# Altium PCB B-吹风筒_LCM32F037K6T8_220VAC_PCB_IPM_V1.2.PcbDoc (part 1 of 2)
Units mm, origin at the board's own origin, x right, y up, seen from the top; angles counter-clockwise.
Board outline 42.33 x 117.1 mm, 2 copper layers (TopLayer, BottomLayer); 131 components, 93 nets, 324 pads, 143 vias.
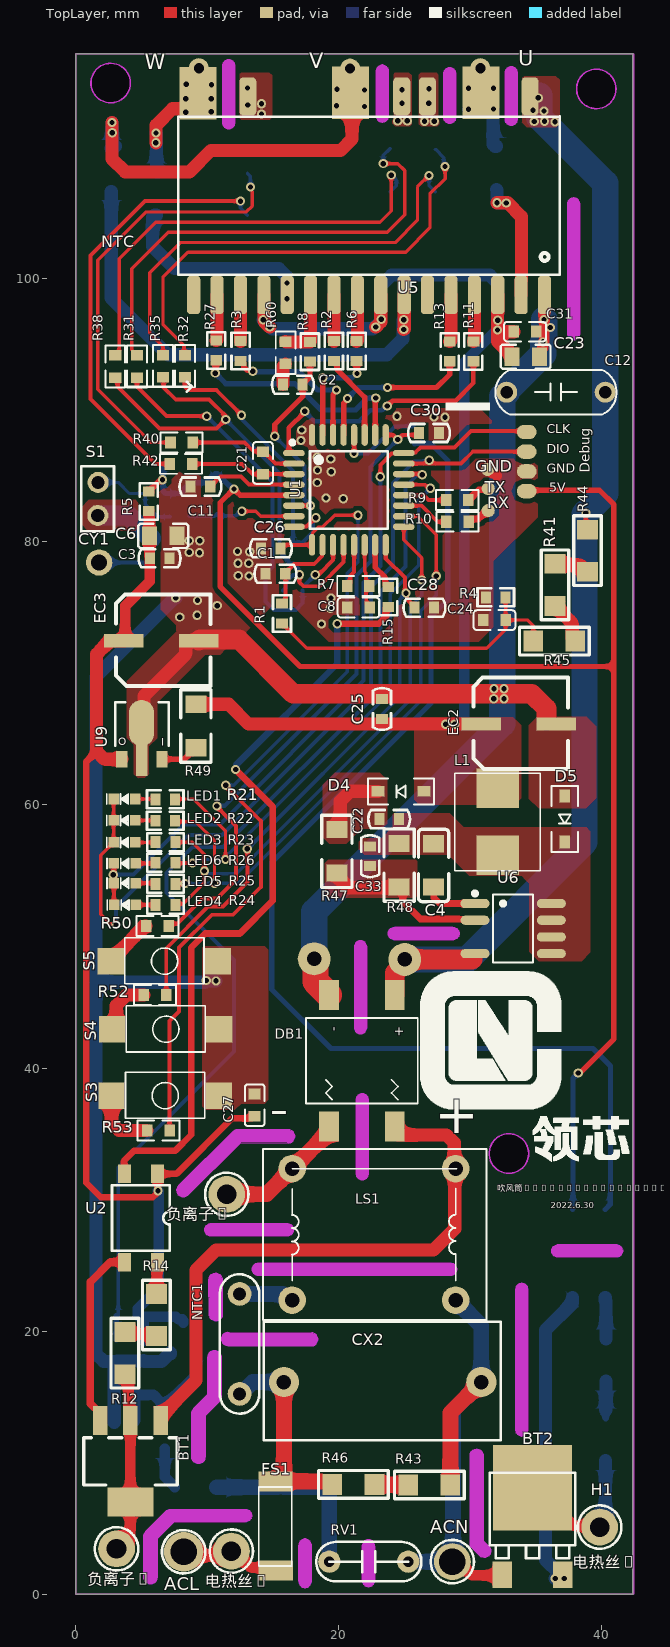
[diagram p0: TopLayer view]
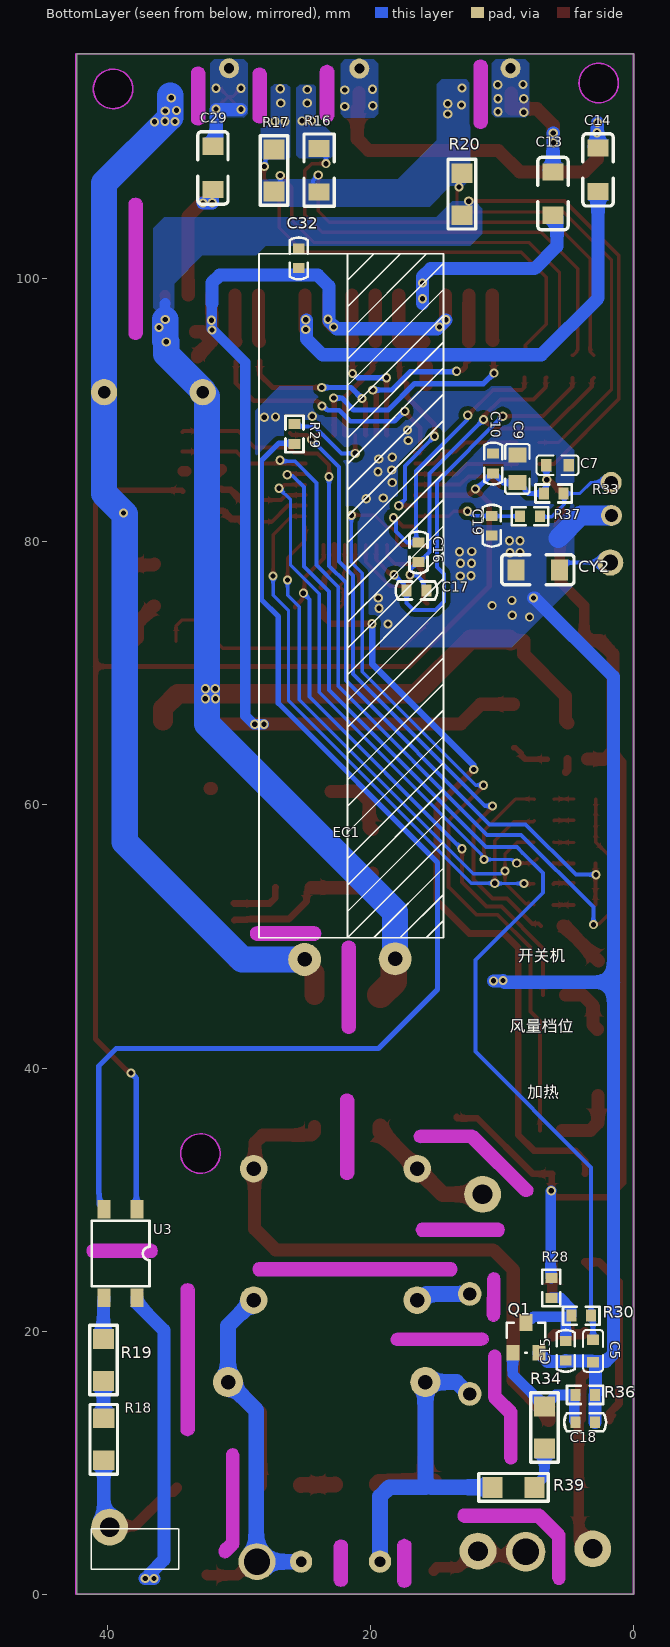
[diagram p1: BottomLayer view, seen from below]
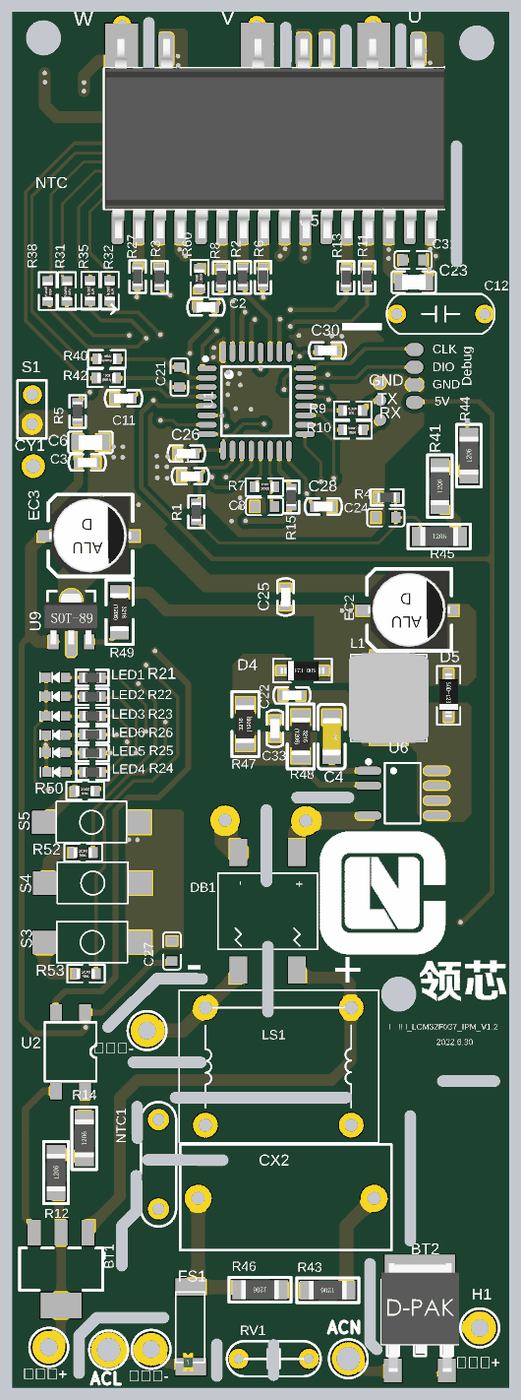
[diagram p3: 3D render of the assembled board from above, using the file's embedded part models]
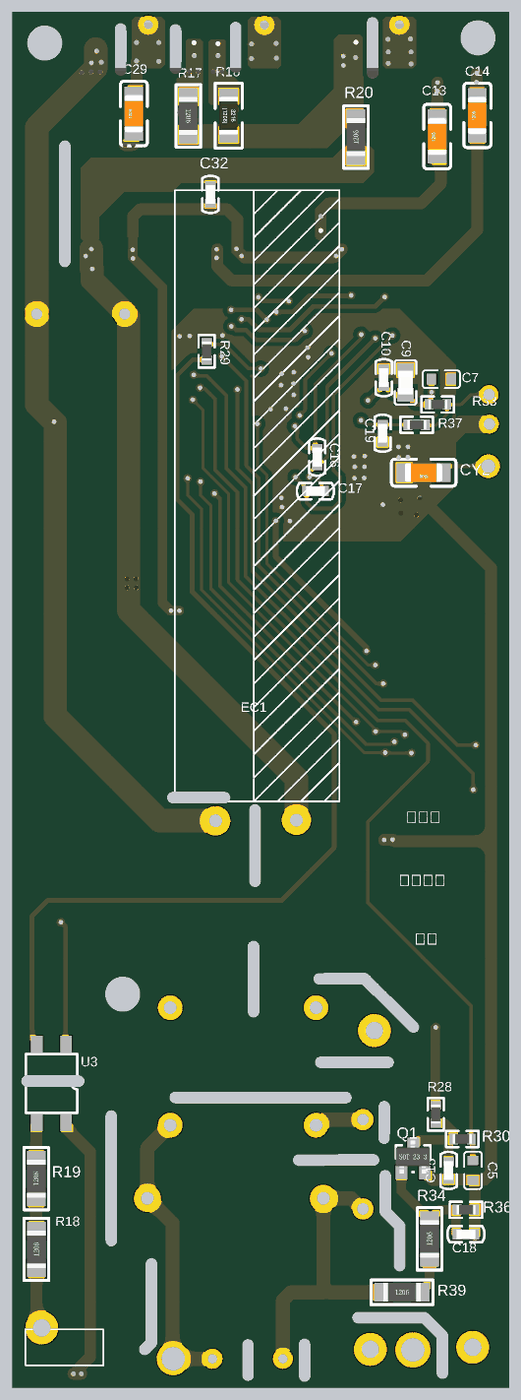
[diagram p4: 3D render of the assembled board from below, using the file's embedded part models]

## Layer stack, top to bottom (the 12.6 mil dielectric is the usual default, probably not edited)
TopSolder: solder mask 0.0102, Solder Resist, Dk 3.5
TopLayer: signal copper 0.035
Dielectric1: dielectric 0.32, FR-4, Dk 4.8
BottomLayer: signal copper 0.035
BottomSolder: solder mask 0.0102, Solder Resist, Dk 3.5

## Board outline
0,0 0,117.1 41,117.1 42.325,117.1 42.325,0
cut-out: 30.121,3.496 cw(c30.475,3.85) 29.975,3.85 29.975,10.55 cw(c30.475,10.55) 30.975,10.55 30.975,4.057 31.404,3.629 cw(c31.05,3.275) 31.55,3.275 cw(c31.05,3.275) 30.696,2.921
cut-out: 5.175,1.25 5.175,4.425 cw(c5.675,4.425) 5.321,4.779 6.871,6.329 cw(c7.225,5.975) 7.225,6.475 12.875,6.475 cw(c12.875,5.975) 13.375,5.975 cw(c12.875,5.975) 12.875,5.475 7.432,5.475 6.175,4.218 6.175,1.25 cw(c5.675,1.25)
cut-out: 21.75,1.075 ccw(c22.25,1.075) 22.75,1.075 22.75,3.65 ccw(c22.25,3.65) 21.75,3.65
cut-out: 16.925,1 ccw(c17.425,1) 17.925,1 17.925,3.7 ccw(c17.425,3.7) 16.925,3.7
cut-out: 7.798,31.056 ccw(c8.15,30.7) 8.502,30.344 12.528,34.322 16.172,34.3 ccw(c16.175,34.8) 16.675,34.8 ccw(c16.175,34.8) 16.178,35.3 12.328,35.324 ccw(c12.324,34.824) 11.972,35.179
cut-out: 11.125,111.9 ccw(c11.625,111.9) 12.125,111.9 12.125,116.15 ccw(c11.625,116.15) 11.125,116.15
cut-out: 8.825,10.4 8.825,13.775 cw(c9.325,13.775) 8.971,14.129 10.05,15.207 10.05,18.05 cw(c10.55,18.05) 11.05,18.05 11.05,15 cw(c10.55,15) 10.904,14.646 9.825,13.568 9.825,10.4 cw(c9.325,10.4)
cut-out: 36.675,25.6 cw(c36.675,26.1) 36.675,26.6 41.075,26.6 cw(c41.075,26.1) 41.575,26.1 cw(c41.075,26.1) 41.075,25.6
cut-out: 33.4,12.525 ccw(c33.9,12.525) 34.4,12.525 34.4,23.125 ccw(c33.9,23.125) 33.4,23.125
cut-out: 10.3,27.2 cw(c10.3,27.7) 10.3,28.2 16.05,28.2 cw(c16.05,27.7) 16.55,27.7 cw(c16.05,27.7) 16.05,27.2
cut-out: 37.35,95.85 ccw(c37.85,95.85) 38.35,95.85 38.35,105.65 ccw(c37.85,105.65) 37.35,105.65
cut-out: 11.548,18.9 17.923,18.875 ccw(c17.925,19.375) 18.425,19.375 ccw(c17.925,19.375) 17.927,19.875 11.552,19.9 ccw(c11.55,19.4)
cut-out: 10.15,21.245 10.125,23.92 cw(c10.625,23.925) 11.125,23.93 11.15,21.255 cw(c10.65,21.252)
cut-out: 31.425,33.5 ccw(c32.925,33.5) 32.925,32 ccw(c32.925,33.5) 34.425,33.5 ccw(c32.925,33.5) 32.925,35 ccw(c32.925,33.5)
cut-out: 38.066,114.428 ccw(c39.566,114.428) 39.566,112.928 ccw(c39.566,114.428) 41.066,114.428 ccw(c39.566,114.428) 39.566,115.928 ccw(c39.566,114.428)
cut-out: 2.65,113.375 cw(c2.65,114.875) 1.15,114.875 cw(c2.65,114.875) 2.65,116.375 cw(c2.65,114.875) 4.15,114.875 cw(c2.65,114.875)
cut-out: 21.275,32 ccw(c21.775,32) 22.275,32 22.275,37.55 ccw(c21.775,37.55) 21.275,37.55
cut-out: 21.15,43.1 ccw(c21.65,43.1) 22.15,43.1 22.15,49.175 ccw(c21.65,49.175) 21.15,49.175
cut-out: 24.25,49.725 cw(c24.25,50.225) 24.25,50.725 28.65,50.725 cw(c28.65,50.225) 29.15,50.225 cw(c28.65,50.225) 28.65,49.725
cut-out: 13.9,24.2 cw(c13.9,24.7) 13.9,25.2 28.45,25.2 cw(c28.45,24.7) 28.95,24.7 cw(c28.45,24.7) 28.45,24.2
cut-out: 27.925,112.3 ccw(c28.425,112.3) 28.925,112.3 28.925,115.55 ccw(c28.425,115.55) 27.925,115.55
cut-out: 32.6,112.15 ccw(c33.1,112.15) 33.6,112.15 33.6,115.625 ccw(c33.1,115.625) 32.6,115.625
cut-out: 22.8,112.4 ccw(c23.3,112.4) 23.8,112.4 23.8,115.75 ccw(c23.3,115.75) 22.8,115.75

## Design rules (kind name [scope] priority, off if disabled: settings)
Clearance [All] p1: gap=0.25 ignorepadtopadclearanceinfootprint=FALSE except(0.35: Arc-Fill Arc-Poly Arc-Region Track-Fill Track-Poly Track-Region SMDPad-Fill SMDPad-Poly SMDPad-Region THPad-Fill THPad-Poly THPad-Region Via-Fill Via-Poly Via-Region Fill-Fill Fill-Poly Fill-Region Poly-Poly Poly-Region Region-Region)
ComponentClearance [All] p1: gap=0 collisioncheckmode=3 verticalgap=2540 showdistances=FALSE
DiffPairsRouting [All] p1: maxlimit=0.254 minlimit=0.254 mostfreqgap=0.254 substack1={7B2B07BE-FECC-4EBA-A35D-CE5C1B368DA4} toplayer_{7b2b07be-fecc-4eba-a35d-ce5c1b368da4}_minwidth=0.381 toplayer_{7b2b07be-fecc-4eba-a35d-ce5c1b368da4}_maxwidth=0.381 toplayer_{7b2b07be-fecc-4eba-a35d-ce5c1b368da4}_prefwidth=0.381 bottomlayer_{7b2b07be-fecc-4eba-a35d-ce5c1b368da4}_minwidth=0.381 bottomlayer_{7b2b07be-fecc-4eba-a35d-ce5c1b368da4}_maxwidth=0.381 bottomlayer_{7b2b07be-fecc-4eba-a35d-ce5c1b368da4}_prefwidth=0.381 substack2={2A57B4B4-6E69-4721-8056-AED80E470A93} toplayer_{2a57b4b4-6e69-4721-8056-aed80e470a93}_minwidth=0.381 toplayer_{2a57b4b4-6e69-4721-8056-aed80e470a93}_maxwidth=0.381 toplayer_{2a57b4b4-6e69-4721-8056-aed80e470a93}_prefwidth=0.381 bottomlayer_{2a57b4b4-6e69-4721-8056-aed80e470a93}_minwidth=0.381 bottomlayer_{2a57b4b4-6e69-4721-8056-aed80e470a93}_maxwidth=0.381 bottomlayer_{2a57b4b4-6e69-4721-8056-aed80e470a93}_prefwidth=0.381 substack3={97241F62-DD6F-472E-8EB9-D48B5CBCBE02} toplayer_{97241f62-dd6f-472e-8eb9-d48b5cbcbe02}_minwidth=0.381 toplayer_{97241f62-dd6f-472e-8eb9-d48b5cbcbe02}_maxwidth=0.381 toplayer_{97241f62-dd6f-472e-8eb9-d48b5cbcbe02}_prefwidth=0.381 bottomlayer_{97241f62-dd6f-472e-8eb9-d48b5cbcbe02}_minwidth=0.381 bottomlayer_{97241f62-dd6f-472e-8eb9-d48b5cbcbe02}_maxwidth=0.381 bottomlayer_{97241f62-dd6f-472e-8eb9-d48b5cbcbe02}_prefwidth=0.381 substack4={361573DB-5FAD-456A-B524-EEB2E02C5D13} toplayer_{361573db-5fad-456a-b524-eeb2e02c5d13}_minwidth=0.381 toplayer_{361573db-5fad-456a-b524-eeb2e02c5d13}_maxwidth=0.381 toplayer_{361573db-5fad-456a-b524-eeb2e02c5d13}_prefwidth=0.381 bottomlayer_{361573db-5fad-456a-b524-eeb2e02c5d13}_minwidth=0.381 bottomlayer_{361573db-5fad-456a-b524-eeb2e02c5d13}_maxwidth=0.381 bottomlayer_{361573db-5fad-456a-b524-eeb2e02c5d13}_prefwidth=0.381 toplayer_minwidth=0.25 toplayer_maxwidth=0.381 toplayer_prefwidth=0.3 bottomlayer_minwidth=0.25 bottomlayer_maxwidth=0.381 bottomlayer_prefwidth=0.3 substack5={64A2AA3D-35F6-4C37-B5AC-204E40DA3198} toplayer_{64a2aa3d-35f6-4c37-b5ac-204e40da3198}_minwidth=0.381 toplayer_{64a2aa3d-35f6-4c37-b5ac-204e40da3198}_maxwidth=0.381 toplayer_{64a2aa3d-35f6-4c37-b5ac-204e40da3198}_prefwidth=0.381 bottomlayer_{64a2aa3d-35f6-4c37-b5ac-204e40da3198}_minwidth=0.381 bottomlayer_{64a2aa3d-35f6-4c37-b5ac-204e40da3198}_maxwidth=0.381 bottomlayer_{64a2aa3d-35f6-4c37-b5ac-204e40da3198}_prefwidth=0.381 substack6={DDE46566-CA28-4514-92A2-DCCB6BB664C3} toplayer_{dde46566-ca28-4514-92a2-dccb6bb664c3}_minwidth=0.381 toplayer_{dde46566-ca28-4514-92a2-dccb6bb664c3}_maxwidth=0.381 toplayer_{dde46566-ca28-4514-92a2-dccb6bb664c3}_prefwidth=0.381 bottomlayer_{dde46566-ca28-4514-92a2-dccb6bb664c3}_minwidth=0.381 bottomlayer_{dde46566-ca28-4514-92a2-dccb6bb664c3}_maxwidth=0.381 bottomlayer_{dde46566-ca28-4514-92a2-dccb6bb664c3}_prefwidth=0.381 substack7={F3E6C291-C9AD-4F5A-A66D-27B9332EED3B} toplayer_{f3e6c291-c9ad-4f5a-a66d-27b9332eed3b}_minwidth=0.381 toplayer_{f3e6c291-c9ad-4f5a-a66d-27b9332eed3b}_maxwidth=0.381 toplayer_{f3e6c291-c9ad-4f5a-a66d-27b9332eed3b}_prefwidth=0.381 bottomlayer_{f3e6c291-c9ad-4f5a-a66d-27b9332eed3b}_minwidth=0.381 bottomlayer_{f3e6c291-c9ad-4f5a-a66d-27b9332eed3b}_maxwidth=0.381 bottomlayer_{f3e6c291-c9ad-4f5a-a66d-27b9332eed3b}_prefwidth=0.381 maxuncoupledlength=12.7
FabricationTestPointUsage TestPointUsage [All] p1: valid=0 allowmultiple=FALSE
FabricationTestpoint Testpoint [All] p1: side=3 testpointundercomponent=TRUE minsize=1.016 maxsize=2.54 preferedsize=1.524 minholesize=0.508 maxholesize=1.016 preferedholesize=0.813 testpointgrid=0.025 allowsidetop=TRUE allowsidebottom=TRUE usegrid=TRUE gridtolerance=0
PolygonConnect [All] p1: connectstyle=Direct reliefconductorwidth=0.254 reliefentries=4 polygonreliefangle="90 Angle" airgapwidth=0.254
RoutingVias [All] p1: holewidth=0.711 width=1.27 viastyle="Through Hole" minholewidth=0.711 minwidth=1.27 maxholewidth=0.711 maxwidth=1.27
SolderMaskExpansion [All] p1: expansion=0.102 istentingtop=FALSE
Width [All] p1: maxlimit=4 minlimit=0.2 preferedwidth=0.254 substack1={7B2B07BE-FECC-4EBA-A35D-CE5C1B368DA4} substack2={2A57B4B4-6E69-4721-8056-AED80E470A93} substack3={97241F62-DD6F-472E-8EB9-D48B5CBCBE02} substack4={361573DB-5FAD-456A-B524-EEB2E02C5D13} substack5={64A2AA3D-35F6-4C37-B5AC-204E40DA3198} substack6={DDE46566-CA28-4514-92A2-DCCB6BB664C3} substack7={F3E6C291-C9AD-4F5A-A66D-27B9332EED3B}
26 further rules are at their usual default settings.

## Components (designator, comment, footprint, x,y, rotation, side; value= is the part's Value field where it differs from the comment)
ACL "发热丝L" TP1.6#1 8.2,3.225 r0 top (schematic designator L-1)
ACN "" TP1.6#2 28.625,2.475 r0 top (schematic designator N2)
BT1 "BT131-600D/SOT223" SOT-223-3_L6.5-W3.4-P2.30-LS7.0-BR 4.15,10.1 r90 top
BT2 "BT138-800E/TO-252" TO-252 34.725,3.975 r0 top
C1 "103/50V" 0603C#1 14.425,77.575 r0 top
C2 "104/50V" 0603C#1 17.25,91.95 r180 top
C3 "10uF/25V" 0603C#1 5.625,78.75 r0 top
C4 "475/25V" C1206C 27.2,55.4 r270 top
C5 "103/50V" 0603C#2 3.075,18.5 r270 bottom
C6 "10uF/10V" 0805C 5.6,80.45 r0 top
C7 "104/50V" 0603C#2 5.775,85.825 r180 bottom
C8 "105/50V" 0603C#2 21.5,75 r0 top value=104/50V
C9 "10uF/25V" 0805C 8.825,84.5 r90 bottom
C10 "104/50V" 0603C#1 10.675,86.7 r270 bottom
C11 "104/50V" 0603C#1 8.725,84.2 r0 top
C12 "104/500V" CAP7.5 36.5,91.375 r0 top value=104P/1KV
C13 "225/50V" C1206C 6.125,106.475 r90 bottom value=100pF
C14 "225/50V" C1206C 2.7,108.275 r90 bottom value=100pF
C15 "103/50V" 0603C#1 5.15,19.25 r270 bottom
C16 "101/50V" 0603C#1 16.35,79.95 r270 bottom
C17 "101/50V" 0603C#1 17.25,76.3 r180 bottom
C18 "103/50V" 0603C#1 4.425,13.075 r180 bottom
C19 "103/50V" 0603C#1 10.775,80.478 r90 bottom
C21 "101/50V" 0603C#2 14.225,86 r270 top
C22 "105/50V" 0603C#1 23.075,58.925 r0 top
C23 "10uF/50V" 0805C 33.15,94.075 r0 top
C24 "103/50V" 0603C#2 31.825,74.05 r180 top
C25 "104/50V" 0603C#1 23.275,66.55 r90 top
C26 "104/50V" 0603C#1 15.575,79.5 r180 top
C27 "104/50V" 0603C#2 13.6,37.175 r90 top
C28 "104/50V" 0603C#1 25.75,75 r0 top
C29 "225/50V" C1206C 31.975,108.425 r90 bottom value=100pF
C30 "104/50V" 0603C#1 26.1,88.275 r0 top
C31 "10uF/50V" 0603C#2 34.15,95.975 r0 top
C32 "104/50V" 0603C#1 25.45,100.8 r90 bottom
C33 "104/50V" 0603C#1 22.375,56.85 r270 top
CX2 "680nF/310VAC" CX0.58UF280VAC-18*9*15-H 23.325,16.125 r180 top
CY1 "" "TP1.6 - 1" 1.775,78.425 r0 top
CY2 "3.3nF/500V" C1206C 7.275,77.875 r0 bottom
D4 "FR107" D-SOD-123 24.725,61.025 r180 top
D5 "ES2JW/SOD123" D-SOD-123 37.175,58.925 r270 top
DB1 "DB307S" DBG-DB107G-SMD 21.75,40.55 r270 top
Debug "CON4" CN4P1.5- 34.275,86.1 r90 bottom
EC1 "120uF/400V 13*45mm" "120UF/400V D18.3*H51.2" 21.475,49.75 r180 bottom locked
EC2 "220uF/25V" ECT6.3_5.5 30.825,66.15 r0 top
EC3 "220uF/16V" ECT6.3_5.5 3.65,72.475 r0 top
FS1 "3.15贴片" "FU 6*2.5" 15.1,5.3 r90 top
GND "P" P 31.3,85.5 r0 top
H1 "发热丝2" TP1.6#3 39.825,5.1 r0 top
L1 "1mH/250mA" LD7*7-SMD 28.825,62.4 r270 top
LED1 "LED" LED0603S 3.7,60.45 r180 top
LED2 "LED" LED0603S 3.7,58.825 r180 top
LED3 "LED" LED0603S 3.7,57.15 r180 top
LED4 "LED" LED0603S 3.75,52.4 r180 top
LED5 "LED" LED0603S 3.725,54.05 r180 top
LED6 "LED" LED0603S 3.725,55.55 r180 top
LS1 "10MH/10*13" "LF-UU9.8 - 1" 20.45,27.325 r90 top
NTC1 "3D-9" CYNTC-P10-S 12.45,19.025 r270 top
Q1 "3904" SOT23SDG-S 8.175,19.5 r180 bottom
R1 "1K" 0603R 15.675,73.8 r90 top
R2 "51R" 0603R 19.625,95.25 r270 top
R3 "51R" 0603R 12.525,95.25 r270 top
R4 "6.8K 1%" 0603R 31.175,75.775 r0 top
R5 "0R 5%" 0603R 5.55,83.825 r270 top
R6 "51R" 0603R 21.35,95.25 r270 top
R7 "10k1% 0603" R0603R 21.475,76.65 r0 top
R8 "1K" 0603R 17.8,95.2 r270 top
R9 "100R 5%" R0603R 29,83.175 r180 top
R10 "100R 5%" R0603R 29.025,81.525 r180 top
R11 "51R" 0603R 30.225,95.225 r270 top
R12 "220R" 1206R#1 3.725,16.725 r90 top
R13 "51R" 0603R 28.425,95.225 r270 top
R14 "220R" 1206R#1 6.125,19.625 r90 top
R15 "330R" 0603R 23.75,76.55 r270 top
R16 "0.15R 1206" 1206R#2 23.9,108.25 r270 bottom
R17 "0.15R 1206" 1206R#1 27.325,109.825 r270 bottom
R18 "220R" 1206R#1 40.275,10.175 r90 bottom
R19 "220R" 1206R#1 40.3,16.2 r90 bottom
R20 "0.15R 1206" 1206R#1 13.05,104.825 r90 bottom
R21 "1K" 0603R 6.05,60.425 r0 top
R22 "1K" 0603R 6.05,58.8 r0 top
R23 "1K" 0603R 6.075,57.175 r0 top
R24 "1K" 0603R 6.075,52.4 r0 top
R25 "1K" 0603R 6.075,54 r0 top
R26 "1K" 0603R 6.075,55.6 r0 top
R27 "51R" 0603R 10.675,95.3 r270 top
R28 "10K" 0603R 6.25,24.025 r270 bottom
R29 "330R" 0603R 25.775,88.95 r270 bottom
R30 "1K" 0603R 4.725,21.175 r180 bottom
R31 "68R/1%" R0603R 4.65,93.325 r270 top
R32 "68R/1%" R0603R 8.3,93.35 r270 top
R33 "20K/1%" 0603R 5.325,83.675 r0 bottom
R34 "215K" 1206R#1 6.775,11.075 r90 bottom
R35 "68R/1%" R0603R 6.625,93.35 r270 top
R36 "4.3K" 0603R 2.925,15.15 r0 bottom
R37 "1K/1%" 0603R 7.125,81.947 r0 bottom
R38 "68R/1%" R0603R 3,93.325 r270 top
R39 "215K" 1206R#1 10.725,8.125 r180 bottom
R40 "68R/1%" R0603R 8.05,87.55 r0 top
R41 "330K 1%" 1206R#1 36.425,75.125 r90 top
R42 "68R/1%" R0603R 8,85.925 r0 top
R43 "330K" 1206R#1 28.475,8.3 r180 top
R44 "330K 1%" 1206R#1 38.9,77.725 r90 top
R45 "330K 1%" 1206R#1 34.775,72.45 r0 top
R46 "330K" 1206R#1 22.7,8.35 r180 top
R47 "2.7K/1%" 1206R#2 19.85,56.475 r90 top
R48 "620R/1%" 1206R#2 24.575,55.425 r270 top
R49 "10R" R1206R 9.125,66 r270 top
R50 "1K" R0603R 6.2,50.8 r180 top
R52 "1K" R0603R 6.025,45.55 r180 top
R53 "1K" R0603R 6.275,35.25 r180 top
R60 "1K" R0603R 15.95,94.375 r90 top
RV1 "7D471" CY2A473J 22.275,2.475 r0 top
RX "P" P 31.35,82.375 r270 top
S1 "" CN2P4 1.675,81.825 r90 top
S3 "KEY" K-3.5*6-SMD 6.8,37.9 r0 top
S4 "KEY" K-3.5*6-SMD 6.85,42.95 r0 top
S5 "KEY" K-3.5*6-SMD 6.75,48.125 r0 top
TX "P" P 31.35,84.05 r270 top
U "" TP1.6-2.5*3.8#1 30.8,113.85 r90 top
U1 "LCM32F037K6T8" LQFP-32 20.55,84 r270 top
U2 "M3052" "SO-4 - 1" 6.2,25.25 r0 top
U3 "M3052" SO-4 37.75,22.55 r180 bottom
U5 "ABS" SOP23 20.85,113.825 r270 top
U6 "PN8015SSC-R1D" SOP-8_L4.9-W3.9-P1.27-LS6.0-BL-PE3 33.25,50.6 r270 top
U9 "78L05" 78L05-SMD 5.025,64.85 r0 top
V "" TP1.6-2.5*3.8#2 20.875,114.15 r90 top
W "" TP1.6-2.5*3.8#2 9.3,114.1 r90 top
电热丝- "" TP1.6#3 11.825,3.275 r0 top (schematic designator ACL)
负离子+ "负离子" TP1.6#3 3.1,3.45 r90 top (schematic designator FULI+1)
负离子- "" TP1.6#3 11.475,30.4 r90 top (schematic designator FULI-1)

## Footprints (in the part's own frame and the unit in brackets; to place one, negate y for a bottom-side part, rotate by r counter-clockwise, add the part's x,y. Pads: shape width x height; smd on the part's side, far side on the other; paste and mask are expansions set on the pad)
78L05-SMD [mm]
  rect 0.864x1.27 smd: 1(1.524,-1.37) 3(-1.524,-1.37)
  oval 1.9x3.5 smd: 2(-0.024,1.37)
  rect 0.864x2.54 smd: 2(0,-1.37)
  silkscreen extent -2.03,-0.35 2.03,2.95, body extent -2.28,-1.57 2.22,2.73, height 1.51
"120UF/400V D18.3*H51.2" [mm]
  round 2.5 hole 1.1: 1(-3.531,-1.499) 2(3.353,-1.448)
  silkscreen extent -7,0.15 7.03,52.15
0603C#1 [mm]
  rect 0.762x0.9 smd: 1(0,0) 2(1.497,0)
  silkscreen extent -0.84,-0.69 2.34,0.69, body extent -0.05,-0.41 1.55,0.4, height 0.89
0603C#2 [mm]
  rect 0.8x0.92 smd: 1(-0.85,0) 2(0.85,0)
  silkscreen extent -1.59,-0.75 1.59,0.75, body extent -0.8,-0.4 0.8,0.4, height 0.3
0603R [mm]
  rect 0.762x0.9 smd: 1(0,0) 2(1.497,0)
  silkscreen extent -0.64,-0.69 2.13,0.69, body extent -0.06,-0.4 1.54,0.4, height 0.46
0805C [mm]
  rect 1.15x1.4 smd: 1(0,0) 2(2.1,0)
  silkscreen extent -0.84,-0.91 2.94,0.91, body extent 0.04,-0.63 2.05,0.62, height 0.93
1206R#1 [mm]
  rect 1.5x1.6 smd: 1(0,0) 2(3.2,0)
  silkscreen extent -1.05,-1.05 4.25,1.05, body extent 0,-0.8 3.2,0.8, height 0.6
1206R#2 [mm]
  rect 1.3x1.6 smd: 1(-1.65,0) 2(1.65,0)
  silkscreen extent -2.75,-1.15 2.75,1.15, body extent -1.6,-0.8 1.6,0.8, height 0.55
C1206C [mm]
  rect 1.3x1.6 smd: 1(-1.65,0) 2(1.65,0)
  silkscreen extent -2.75,-1.15 2.75,1.15, body extent -1.6,-0.8 1.6,0.8, height 1
CAP7.5 [mm]
  round 1.6 / inner round 2 / far side round 2 hole 0.95: 1(-3.75,0) 2(3.75,0)
  silkscreen extent -4.61,-1.7 4.61,1.7
CN2P4 [mm]
  round 1.6 hole 1: 1(0.178,0) 2(2.692,-0.025)
  silkscreen extent -1.04,-1.23 3.91,1.25
CN4P1.5- [mm]
  oval 1.1x1.5 smd far side: 1(-2.25,0) 2(-0.75,0) 3(0.75,0) 4(2.25,0)
CX0.58UF280VAC-18*9*15-H [mm]
  round 2.3 hole 1.1: 1(-7.5,0) 2(7.5,0)
  silkscreen extent -8.97,-4.59 9.03,4.41
CY2A473J [mm]
  round 1.7 hole 0.8: 1(-3,0) 2(3,0)
  silkscreen extent -4,-1.5 4,1.5
CYNTC-P10-S [mm]
  round 1.8 hole 1: 1(3.8,0) 2(-3.8,0)
  silkscreen extent -5.3,-1.5 5.3,1.5
D-SOD-123 [mm]
  rect 1x0.8 smd: 1(-1.75,0) 2(1.75,0)
  silkscreen extent -2.5,-1 2.5,1, body extent -1.85,-0.8 1.85,0.8, height 1.2
DBG-DB107G-SMD [mm]
  rect 2.3x1.5 smd: 1(5,-2.5) 2(-5,2.5) 3(5,2.5) 4(-5,-2.5)
  silkscreen extent -3.25,-4.25 3.25,4.25
ECT6.3_5.5 [mm]
  rect 3x1 smd: 1(0,0) 2(5.7,0)
  silkscreen extent -0.6,-3.43 6.6,3.53, body extent -0.53,-3.25 6.47,3.35, height 5.4
"FU 6*2.5" [mm] "贴片保险丝"
  rect 1.5x2.6 smd: 1(-3.505,-0.102) 2(3.277,-0.076)
  silkscreen extent -3.15,-1.31 2.85,1.19, body extent -3.92,-0.28 -2.32,0.54, height 0.52
K-3.5*6-SMD [mm]
  rect 2x2 smd: 1(-4.089,0) 2(4.064,0)
  silkscreen extent -3.02,-1.73 3,1.78
LD7*7-SMD [mm]
  rect 3x3.2 smd: 1(1.143,3.25) 2(6.223,3.25)
  silkscreen extent 0,0 7.4,6.5, body extent -0.1,-0.16 7.5,6.64, height 4.39
LED0603S [mm]
  rect 0.8x0.8 smd: 1(-0.825,0) 2(0.825,0)
  silkscreen extent -0.3,-0.4 1.35,0.4
"LF-UU9.8 - 1" [mm]
  round 2.1 hole 1.1: 1(-4.975,-8.425) 2(-4.975,4) 3(5.025,-8.425) 4(5.025,4)
  silkscreen extent -6.48,-10.77 6.52,6.23
LQFP-32 [mm]
  oval 0.48x1.65 smd: 1(-2.748,-3.968) 2(-1.948,-3.968) 3(-1.148,-3.968) 4(-0.348,-3.968) 5(0.452,-3.968) 6(1.252,-3.968) 7(2.052,-3.968) 8(2.852,-3.968) 17(2.852,4.382) 18(2.052,4.382) 19(1.252,4.382) 20(0.452,4.382) 21(-0.348,4.382) 22(-1.148,4.382) 23(-1.948,4.382) 24(-2.748,4.382)
  oval 1.65x0.48 smd: 9(4.227,-2.593) 10(4.227,-1.793) 11(4.227,-0.993) 12(4.227,-0.193) 13(4.227,0.607) 14(4.227,1.407) 15(4.227,2.207) 16(4.227,3.007) 25(-4.123,3.007) 26(-4.123,2.207) 27(-4.123,1.407) 28(-4.123,0.607) 29(-4.123,-0.193) 30(-4.123,-0.993) 31(-4.123,-1.793) 32(-4.123,-2.593)
  silkscreen extent -3.7,-4.24 3,3.16
P [mm]
  round 1 smd: 1(0,0)
R0603R [mm]
  rect 0.8x0.92 smd: 1(-0.85,0) 2(0.85,0)
  silkscreen extent -1.6,-0.75 1.6,0.75, body extent -0.75,-0.4 0.8,0.45, height 0.45
R1206R [mm]
  rect 1.3x1.6 smd: 1(-1.65,0) 2(1.65,0)
  silkscreen extent -2.75,-1.15 2.75,1.15, body extent -1.6,-0.8 1.6,0.8, height 0.55
SO-4 [mm]
  rect 1x1.4 smd: 1(0,6.7) 2(-2.5,6.7) 3(-2.5,0) 4(0,0)
  silkscreen extent -3.45,0.85 0.95,5.85
"SO-4 - 1" [mm]
  rect 1x1.4 smd: 1(0,6.7) 2(-2.5,6.7) 3(0,0) 4(-2.5,0)
  silkscreen extent -3.45,0.85 0.95,5.85
SOP23 [mm]
  rrect50% 2.9x1 smd: 1(15.066,14.782) 2(15.066,13.004) 3(15.066,11.226) 4(15.066,9.448) 5(15.066,7.67) 6(15.066,5.892) 7(15.066,4.114) 8(15.066,2.336) 9(15.066,0.558) 10(15.066,-1.22) 11(15.066,-2.998) 12(15.066,-4.776) 13(15.066,-6.554) 14(15.066,-8.332) 15(15.066,-10.11) 16(15.066,-11.888)
  rrect50% 2.9x1.3 smd: 17(-0.034,13.677) 18(-0.034,9.777) 19(-0.034,5.877) 20(-0.034,3.927) 21(-0.034,0.027) 22(-0.034,-7.773) 23(-0.034,-11.673)
  silkscreen extent 1.47,-13.05 13.52,15.95, body extent -0.95,-12.97 16,16.03, height 3.5
SOP-8_L4.9-W3.9-P1.27-LS6.0-BL-PE3 [mm]
  oval 0.7x2.2 smd: 1(-1.905,-2.902) 2(-0.635,-2.902) 4(1.905,-2.902) 5(1.905,2.902) 6(0.635,2.902) 7(-0.635,2.902) 8(-1.905,2.902)
  silkscreen extent -2.82,-3.05 2.58,1.52
SOT23SDG-S [mm]
  rect 1x1.2 smd: 1(-1,-1.15) 2(1,-1.15)
  rect 1x1.27 smd: 3(0,1.15)
  silkscreen extent -1.46,-1.14 1.46,1.14, body extent -1.48,-1.25 1.42,1.55, height 1.2
SOT-223-3_L6.5-W3.4-P2.30-LS7.0-BR [mm]
  rect 2.2x1.1 smd: 1(3.099,-2.3) 2(3.099,0) 3(3.099,2.3)
  rect 2.2x3.5 smd: 2(-3.099,0)
  silkscreen extent -1.8,-3.55 1.8,3.55
TO-252 [mm]
  rect 1.5x2 smd: 1(-2.3,-2.5) 3(2.3,-2.5)
  rect 6x6.5 smd: 2(0,4.1)
  silkscreen extent -3.25,-1.25 3.25,5.25, body extent -3.27,-2.62 3.33,6.63, height 2.31
TP1.6#1 [mm]
  round 3 hole 2: 1(0,0)
  silkscreen extent -1.65,-1.65 1.65,1.65
TP1.6#2 [mm]
  round 2.8 hole 2: 1(0,0)
  silkscreen extent -1.65,-1.65 1.65,1.65
TP1.6#3 [mm]
  round 2.8 hole 1.5: 1(0,0)
  silkscreen extent -1.65,-1.65 1.65,1.65
"TP1.6 - 1" [mm]
  round 2 hole 1.2: 1(0,0)
TP1.6-2.5*3.8#1 [mm]
  rect 4x2.8 smd: 1(0.3,0)
TP1.6-2.5*3.8#2 [mm]
  rect 4x2.8 smd: 1(0,0)

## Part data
ACL ACN CY1 H1 U V W 电热丝- 负离子+: library part CON1, "Connector"
BT1 BT2: library part TRIAC
C1 C2 C3 C5 C6 C7 C10 C11 C19 C22 C23 C24 C25 C27 C31 C32 CY2: library part CAP
C4 C12 C33: library part Cap, "Capacitor"
C8 C9 CX2: library part CAP, "Capacitor"
C13 C14 C15 C18 C29: library part Cap
C16 C17 C21 C26 C28 C30: library part C_SMD, "贴片 无极性电容"
D4 D5: library part DIODE
DB1: library part BRIDGE2, "Diode Bridge"
EC1 EC2 EC3: library part ELE
FS1: library part "Fuse 1", "Fuse"
L1: library part INDUCTOR
LS1: library part TRANS1, "8MH"
NTC1 RV1: library part "Res Varistor", "Varistor (Voltage-Sensitive Resistor)"
Q1: library part NPN/SOT-89/BCE
R1 R4 R12 R14 R15 R16 R17 R18 R19 R20 R21 R22 R23 R24 R25 R26 R28 R29 R30 R33 R34 R36 R37 R39 R41 R43 R44 R45 R46 R47 R48 R49: library part RES2
R2 R3 R6 R8 R11 R13 R27 R60: library part RES1
R5 R7 R9 R10: library part RES
R31 R32 R35 R38 R40 R42 R50 R52 R53: library part R_SMD, "贴片 电阻器"
S1: library part CON2, "Connector"
S3 S4 S5: library part SW
U2 U3: library part OPTOTRIAC
U5: library part XNS50660AB, BOM_JLCPCB Part Class="Extended Part", BOM_Manufacturer=XINER
U6: BOM_Manufacturer=chipown(芯朋微电子)
负离子-: library part CON1, "负离子L"

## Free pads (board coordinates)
  round 1.524 hole 0.762: 458(9.35,116) 459(20.85,115.975) 460(30.75,116)

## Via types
v1: diameter 0.7, hole 0.4, TopLayer to BottomLayer, tented both sides, 133 vias
v2: diameter 0.7, hole 0.4, TopLayer to BottomLayer, 10 vias

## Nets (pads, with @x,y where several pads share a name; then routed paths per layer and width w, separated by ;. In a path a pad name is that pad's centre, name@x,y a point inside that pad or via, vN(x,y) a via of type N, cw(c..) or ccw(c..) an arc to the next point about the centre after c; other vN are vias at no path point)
5V: C3.1 C6.1 C27.1 EC3.1 R5.2 R28.1 U2.1 U9.3 | length 79
  TopLayer w0.5: 1.575,64.066 0.8,63.291 0.8,31.275 1.9,30.175 5.857,30.175 6.15,30.468 6.15,30.521 6.25,30.621 v1(6.25,30.675) 6.225,30.7 6.225,31.925 U2.1@6.2,31.95 7.65,31.95 11.875,36.175 13.39,36.175 13.425,36.21 C27.1@13.425,36.3
  TopLayer w0.8: EC3.1@3.75,72.6 3.75,75.125 5.625,77 C3.1@5.625,78.75 5.606,78.769 5.606,78.925 5.6,78.931 C6.1@5.6,80.45 5.6,82.309 5.581,82.328 R5.2@5.55,82.328
  TopLayer w1: U9.3@3.501,63.48 2.161,63.48 1.575,64.066 1.575,71.475 2.575,72.475 EC3.1@3.65,72.475
  BottomLayer w0.8: R28.1@6.25,24.025 6.269,24.044 6.3,24.044 6.3,30.625 v1(6.25,30.675)
15V: C23.1 C25.1 C31.1 C32.1 D4.1 EC2.1 L1.1 R49.1 U5.3 U5.8 U5.13 | length 92.5
  TopLayer w1: R49.1@9.125,67.65 11.625,67.65 13.125,66.15 28.8,66.15 EC2.1@30.825,66.15 EC2.1@31.825,66.15 ; U5.13@14.296,98.759 14.296,96.779 v1(14.75,96.325) ; v1(22.8,96.325) 23.186,96.711 U5.8@23.186,98.759 ; L1.1@32.075,61.257 L1.1@32.175,61.257 ; U5.3@32.076,98.759 32.076,97.411 32.051,97.386 32.051,95.312 32.054,95.309 32.054,95.25 ; C23.1@33.15,94.075 33.15,94.2 33.075,94.275 33.029,94.275 32.054,95.25 ; C31.1@33.3,95.975 32.779,95.975 32.054,95.25
  BottomLayer w0.8: v1(28.1,66.125) v1(28.8,66.125) 28.881,66.125 29.525,66.769 29.525,93.65 32.075,96.2 v1(32.075,96.85) ; v1@32.054,96.954 32.054,98.125
  BottomLayer w1: v1(14.25,96.875) 14.925,96.2 22.578,96.2 23.164,96.786 23.164,99.439 24,100.275 31.468,100.275 32.054,99.689 32.054,98.125
  other v1: 32.05,96.1 23.225,96.925
ACL: ACL.1 FS1.1 电热丝-.1 | length 7.8
  TopLayer w0.8: ACL.1@8.2,3.225 8.533,2.892 电热丝-.1@11.825,2.892 ; 电热丝-.1@11.825,3.275 12.052,3.275 13.294,2.034 14.963,2.034 FS1.1@15.202,1.795
ACL1: CX2.2 FS1.2 NTC1.1 R39.1 R46.2 RV1.1 | length 37.9
  TopLayer w0.8: RV1.1@19.103,2.647 RV1.1@19.275,2.475
  TopLayer w1.2: FS1.2@15.176,8.577 15.276,8.577 18.647,8.577 18.674,8.55 19.35,8.55 19.5,8.4 R46.2@19.5,8.35 ; FS1.2@15.675,8.577 15.825,8.727 CX2.2@15.825,16.125
  BottomLayer w1.2: R39.1@10.725,8.125 12.925,8.125 15.356,8.125 15.591,8.359 ; NTC1.1@12.45,15.225 12.553,15.225 13.453,16.125 CX2.2@15.825,16.125 15.825,8.594 15.591,8.359 ; RV1.1@19.275,2.475 19.275,7.422 18.572,8.125 15.825,8.125 15.591,8.359
ACL2: DB1.1 LS1.4 负离子-.1 | length 10.1
  TopLayer w1.2: 负离子-.1@11.475,30.4 14.5,30.4 LS1.4@16.45,32.35 19.25,35.15 DB1.1@19.25,35.55
ACN: ACN.1 BT2.1 CX2.1 LS1.1 R43.1 RV1.2 | length 38
  TopLayer w0.8: ACN.1@28.625,2.475 29.094,2.475 30.144,1.425 32.375,1.425 BT2.1@32.425,1.475
  TopLayer w1.2: R43.1@28.475,8.3 28.475,13.775 CX2.1@30.825,16.125
  BottomLayer w1.2: RV1.2@25.275,2.475 ACN.1@28.625,2.475 28.675,2.525 28.675,13.975 CX2.1@30.825,16.125 30.825,20.4 LS1.1@28.875,22.35
ACN1: BT1.1 DB1.3 LS1.3 | length 45.5
  TopLayer w1: BT1.1@6.45,13.199 6.45,13.749 6.5,13.799 6.699,13.799 9.15,16.25 9.15,24.65 10.675,26.175 27.2,26.175 28.809,27.784 28.809,32.284 LS1.3@28.875,32.35 28.775,32.45 28.775,34.314 28.189,34.9 24.5,34.9 24.25,35.15 DB1.3@24.25,35.55
COM1: Debug.3 LED1.2 LED2.2 LED3.2 U1.23 | length 67.9
  TopLayer w0.25: LED1.2@2.875,60.45 LED2.2@2.875,58.825 LED3.2@2.875,57.15 1.9,56.175 1.9,51.675 2.6,50.975 2.975,50.975 v1(3.05,50.9)
  TopLayer w0.3: U1.23@24.932,85.948 v1@26.912,85.948 ; v1(26.875,86.2) 26.936,86.139 26.936,85.95 29.275,85.95 30.175,86.85 Debug.3@34.275,86.85
  BottomLayer w0.3: v1(3.05,50.9) 3.05,52.225 8.55,57.725 11.125,57.725 22.45,69.05 22.45,76.575 24.1,78.225 24.1,84.475 25.75,86.125 26.8,86.125 v1(26.875,86.2)
COM2: Debug.4 LED4.2 LED5.2 LED6.2 U1.24 | length 57.4
  TopLayer w0.3: LED6.2@2.9,55.55 LED5.2@2.9,54.05 2.9,52.425 LED4.2@2.925,52.4 ; v1(23.15,84.95) 23.15,85.85 24.014,86.714 U1.24@24.932,86.714 ; U1.24@24.932,86.748 24.966,86.782 25.807,86.782 26.2,87.175 28.8,87.175 30.05,88.425 34.2,88.425 Debug.4@34.275,88.35
  BottomLayer w0.3: v1(2.85,54.7) 4.375,54.7 8.2,58.525 10.95,58.525 21.875,69.45 21.875,76.9 23.15,78.175 v1(23.15,84.95)
FULZ: R15.1 U1.15 | length 3.7
  TopLayer w0.4: U1.15@22.757,79.773 22.757,78.068 23.5,77.325 23.5,76.731 23.681,76.55 R15.1@23.75,76.55
GND: C1.1 C3.2 C5.2 C6.2 C7.2 C8.1 C9.2 C10.1 C11.1 C12.1 C15.2 C18.2 C19.1 C23.2 C24.2 C25.2 C26.2 C27.2 C28.2 C30.2 C31.2 C32.2 CY2.2 D5.1 DB1.4 Debug.2 EC1.2 EC2.2 EC3.2 GND.1 Q1.2 R4.1 R20.1 R36.1 R42.1 S1.1 S3.2 S4.2 S5.2 U1.32 U5.1 U9.2 | length 224.9
  TopLayer w0.3: R42.1@7.15,85.925 6.05,85.925 1.125,90.85 1.125,101.775 5.25,105.9 v1(12.525,105.9)
  TopLayer w0.6: U9.2@5.025,63.48 5.025,62.642 U9.2@5.157,62.51
  TopLayer w0.8: DB1.4@18.9,46.3 19.25,45.95 DB1.4@19.25,45.55 ; GND.1@31.3,85.5 31.354,85.5 31.654,85.2 31.826,85.2 32.001,85.025 ; Debug.2@33.994,85.35 Debug.2@34.275,85.35 ; C23.2@35.25,94.075 35.425,94.25 35.425,94.665 35.525,94.765 v1(35.525,95.2) 35.61,95.285 35.61,98.737 U5.1@35.632,98.759
  TopLayer w1: U9.2@5.001,66.22 5.173,66.392 5.173,68.273 8.35,71.45 8.35,72.475 EC3.2@9.35,72.475
  TopLayer w1.5: EC3.2@9.35,72.475 9.45,72.575 12.4,72.575 16.525,68.45 32.075,68.45 34.646,68.45 35.775,67.321 EC2.2@35.775,66.4
  TopLayer w2: EC1.2@18.122,48.302 18.218,48.207 18.218,46.582 DB1.4@19.25,45.55
  BottomLayer w0.254: v1(12.525,105.9) 12.525,105.35 R20.1@13.05,104.825
  BottomLayer w0.8: 35.61,98.125 35.625,98.11 v1@35.625,96.8
  BottomLayer w1: C18.2@2.928,13.075 2.928,13.175 2.925,13.178 R36.1@2.925,15.15 2.9,15.175 2.9,17.475 C5.2@3.075,17.65 ; Q1.2@7.175,18.35 7.175,18.25 7.075,18.25 6.519,17.694 5.209,17.694 C15.2@5.15,17.753 5.122,17.725 3.15,17.725 C5.2@3.075,17.65 ; v1(7.6,75.725) 7.5,75.725 1.525,69.75 1.525,46.525 ; v1@9.925,46.625 v1(10.65,46.625) ; v1(9.925,46.65) 9.8,46.525 1.525,46.525 ; 1.525,46.525 1.525,18.286 2.111,17.7 3.025,17.7 C5.2@3.075,17.65
  BottomLayer w1.5: S1.1@1.675,82.003 3.997,82.003 5.725,80.275
  BottomLayer w2: EC1.2@18.122,48.302 18.13,48.31 18.13,51.88 32.425,66.175 32.425,68.325 32.425,91.05 C12.1@32.75,91.375 32.75,91.5 35.525,94.275 v1(35.525,95.2) 35.6,95.275 v1(35.6,96.9)
  other v1: 31.775,68.075 32.55,68.075 31.8,68.825 32.55,68.825 18.675,73.75 7.9,74.275 9.225,74.425 19.35,74.95 10.75,75.15 9.25,75.55 19.401,75.729 13.175,77.4 12.35,77.425 12.325,78.375 13.15,78.375 9.4,79.175 8.625,79.2 13.225,79.25 12.3,79.275 8.625,80.075 9.425,80.075 20.325,83.275 19.025,83.325 18.35,84.5 19.425,85.325 18.375,85.45 19.375,86.3 18.35,86.425 17.125,87.7 17.175,88.5 28.075,89.475 27.225,89.5 24.425,89.55 36.075,96.3
HEAT: R29.1 U1.28 | length 6.9
  TopLayer w0.3: v1(21.15,86.725) 21.157,86.732 U1.28@21.157,88.123
  BottomLayer w0.3: v1(21.15,86.725) 22.2,86.725 24.25,88.775 25.6,88.775 R29.1@25.775,88.95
